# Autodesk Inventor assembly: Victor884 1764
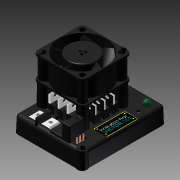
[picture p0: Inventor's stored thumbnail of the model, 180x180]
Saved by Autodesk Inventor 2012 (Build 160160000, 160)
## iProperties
Shininess: 64.0
Length Units: 11272
Angle Units: 11279
Time Units: 11290
Mass Units: 11286
Length Display Precision: 3
Angle Display Precision: 2
Compacted: True
Part Number: Victor884 1764
Document SubType Name: Assembly
Created: 2007-01
Designer: uidk0133
Density: 0.0
Volumn: 0.0
Area: 0.0
PropertySet Name: Model Information
Control State: 0
Master: False
Checked Out: False
Author: uidk0133
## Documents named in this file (9)
- R:\CAD Archives\Electronics_1764\Victor_884_1764\Victor884_1764.iam
- R:\CAD Archives\Electronics_1764\Victor_884_1764\Victor_Cover_1764.ipt
- R:\CAD Archives\Electronics_1764\Victor_884_1764\Victor_Fan_1764.ipt
- R:\CAD Archives\Electronics_1764\Victor_884_1764\Victor_Base_1764.ipt
- R:\CAD Archives\Electronics_1764\Victor_884_1764\Victor_Capacitor_1764.ipt
- R:\CAD Archives\Electronics_1764\Victor_884_1764\Victor_LED_Green_1764.ipt
- R:\CAD Archives\Electronics_1764\Victor_884_1764\Victor_Fet_1764.ipt
- R:\CAD Archives\Electronics_1764\Victor_884_1764\Victor_Screw_Terminal_1764.ipt
- R:\CAD Archives\Electronics_1764\Victor_884_1764\Victor_3_Pin_Connector_1764.ipt
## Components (22 placed, 8 different names)
1. Victor_Cover_1764:1 — Mate:1, Mate:2, Mate:3, Mate:4, Mate:5, Angle:1, Mate:6, Mate:7, Mate:8, Mate:9, Flush:2, Flush:3, Flush:4, Flush:9, Flush:13, Mate:12
2. Victor_Fan_1764:1 — Mate:4, Mate:5, Angle:1, Flush:1, Flush:10, Mate:10, Mate:13, Mate:14
3. Victor_Base_1764:1 — Mate:1, Mate:2, Mate:3
4. Victor_Capacitor_1764:1 — Mate:6, Flush:13
5. Victor_LED_Green_1764:1 — Mate:7, Mate:8
6. Victor_3_Pin_Connector_1764:1 — Mate:12, Mate:13, Mate:14
7. Victor_Fet_1764:14 — Flush:3, Flush:6, Flush:8
8. Victor_Fet_1764:15 — Flush:4, Flush:5, Flush:7, Flush:8
9. Victor_Fet_1764:13 — Mate:9, Flush:1, Flush:2, Flush:5, Flush:6, Flush:7
10. Victor_Fet_1764:16
11. Victor_Fet_1764:17
12. Victor_Fet_1764:18
13. Victor_Fet_1764:19
14. Victor_Fet_1764:20
15. Victor_Fet_1764:21
16. Victor_Fet_1764:22
17. Victor_Fet_1764:23
18. Victor_Fet_1764:24
19. Victor_Screw_Terminal_1764:5 — Flush:9, Flush:10, Mate:10, Flush:11, Flush:12, Mate:11
20. Victor_Screw_Terminal_1764:6 — Flush:11, Flush:12, Mate:11
21. Victor_Screw_Terminal_1764:7
22. Victor_Screw_Terminal_1764:8
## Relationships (28: Mate 14, Flush 13, Angle 1)
- Mate:1: Victor_Cover_1764:1 ↔ Victor_Base_1764:1
- Mate:2: Victor_Cover_1764:1 ↔ Victor_Base_1764:1
- Mate:3: Victor_Cover_1764:1 ↔ Victor_Base_1764:1
- Mate:4: Victor_Cover_1764:1 ↔ Victor_Fan_1764:1
- Mate:5: Victor_Cover_1764:1 ↔ Victor_Fan_1764:1
- Angle:1: Victor_Cover_1764:1 ↔ Victor_Fan_1764:1
- Mate:6: Victor_Cover_1764:1 ↔ Victor_Capacitor_1764:1
- Mate:7: Victor_Cover_1764:1 ↔ Victor_LED_Green_1764:1
- Mate:8: Victor_Cover_1764:1 ↔ Victor_LED_Green_1764:1
- Mate:9: Victor_Cover_1764:1 ↔ Victor_Fet_1764:13
- Flush:1: Victor_Fan_1764:1 ↔ Victor_Fet_1764:13
- Flush:2: Victor_Cover_1764:1 ↔ Victor_Fet_1764:13
- Flush:3: Victor_Cover_1764:1 ↔ Victor_Fet_1764:14
- Flush:4: Victor_Cover_1764:1 ↔ Victor_Fet_1764:15
- Flush:5: Victor_Fet_1764:15 ↔ Victor_Fet_1764:13
- Flush:6: Victor_Fet_1764:14 ↔ Victor_Fet_1764:13
- Flush:7: Victor_Fet_1764:15 ↔ Victor_Fet_1764:13
- Flush:8: Victor_Fet_1764:14 ↔ Victor_Fet_1764:15
- Flush:9: Victor_Cover_1764:1 ↔ Victor_Screw_Terminal_1764:5
- Flush:10: Victor_Fan_1764:1 ↔ Victor_Screw_Terminal_1764:5
- Mate:10: Victor_Fan_1764:1 ↔ Victor_Screw_Terminal_1764:5
- Flush:11: Victor_Screw_Terminal_1764:5 ↔ Victor_Screw_Terminal_1764:6
- Flush:12: Victor_Screw_Terminal_1764:5 ↔ Victor_Screw_Terminal_1764:6
- Mate:11: Victor_Screw_Terminal_1764:5 ↔ Victor_Screw_Terminal_1764:6
- Flush:13: Victor_Cover_1764:1 ↔ Victor_Capacitor_1764:1
- Mate:12: Victor_Cover_1764:1 ↔ Victor_3_Pin_Connector_1764:1
- Mate:13: Victor_Fan_1764:1 ↔ Victor_3_Pin_Connector_1764:1
- Mate:14: Victor_Fan_1764:1 ↔ Victor_3_Pin_Connector_1764:1
